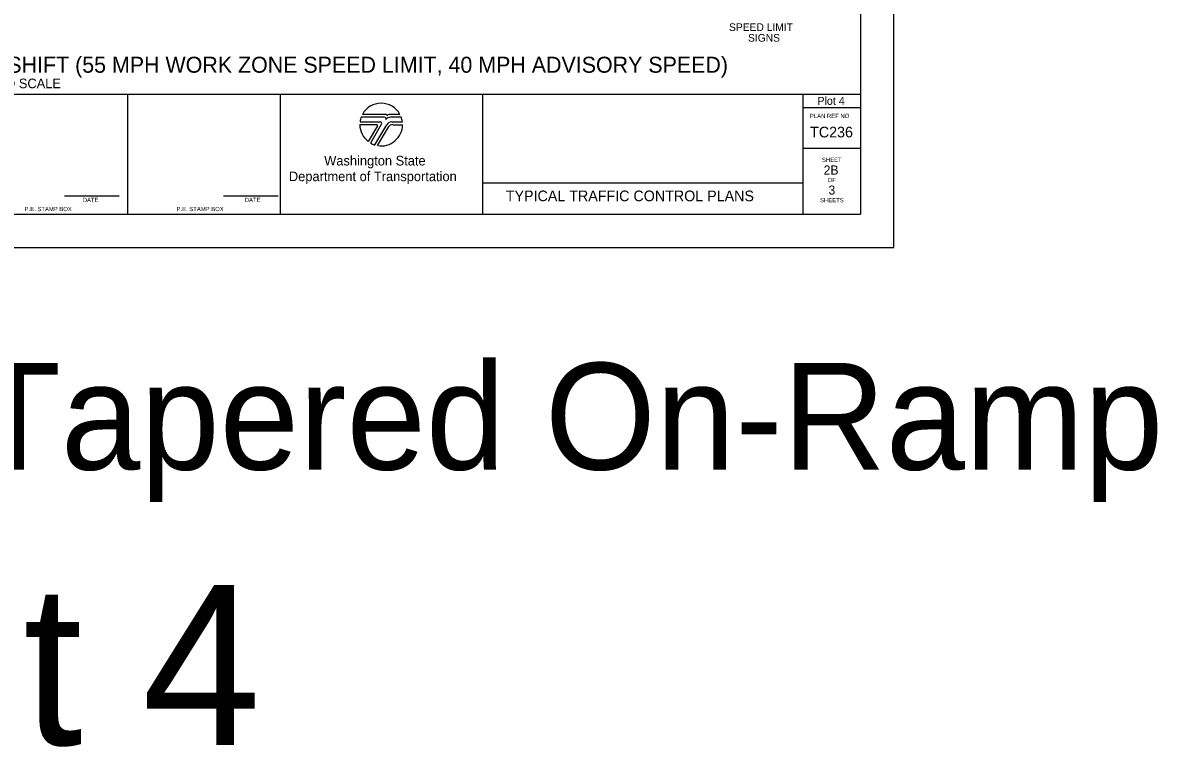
# Model space of a CAD drawing. Extents: x 99999 to 100116, y 99995 to 100013.
# Drawn here: x 100067.9 to 100078.53, y 99995.01 to 100001.79 of the extents above; entities that cross this region are included whole.
import ezdxf

# ---------------------------------------------------------------- set-up
doc = ezdxf.new("R2010")
doc.units = 0
for name, color, linetype in [('SH_DE_DetailHeading1Text', 7, 'Continuous'), ('SH_GI_PlotLimits', 7, 'Continuous'), ('SH_GI_SheetBorder', 7, 'Continuous'), ('SH_GI_SheetLocationText', 7, 'Continuous'), ('SH_GI_SheetTextInCells', 7, 'Continuous'), ('SH_GI_TitleBlockText', 7, 'Continuous'), ('SH_GI_WSDOTLogo', 7, 'Continuous'), ('TR_SN_ConstructionSigns', 7, 'Continuous')]:
    doc.layers.add(name, color=color, linetype=linetype)

msp = doc.modelspace()

# ---------------------------------------------------------------- linework, layer by layer
at = {"layer": 'SH_GI_PlotLimits'}
msp.add_lwpolyline([(100059.062, 99999.687), (100076.062, 99999.687), (100076.062, 100010.687), (100059.062, 100010.687)], close=True, dxfattribs=at)
at = {"layer": 'SH_GI_SheetBorder'}
for p, q in [((100075.75, 100010.375), (100075.75, 100000)), ((100060, 100001.126), (100075.75, 100001.126)), ((100068.883, 100000), (100068.883, 100001.126)), ((100070.309, 100001.126), (100070.309, 100000)), ((100072.205, 100001.126), (100072.205, 100000)), ((100075.208, 100001.126), (100075.208, 100000)), ((100075.208, 100001.001), (100075.75, 100001.001)), ((100075.208, 100000.618), (100075.75, 100000.618)), ((100072.205, 100000.295), (100075.208, 100000.295)), ((100068.29, 100000.173), (100068.802, 100000.173)), ((100069.78, 100000.173), (100070.291, 100000.173)), ((100060, 100000), (100075.75, 100000))]:
    msp.add_line(p, q, dxfattribs=at)
at = {"layer": 'SH_GI_WSDOTLogo'}
for p, q in [((100071.303, 100000.935), (100071.081, 100000.935)), ((100071.433, 100000.935), (100071.335, 100000.935)), ((100071.057, 100000.84), (100071.215, 100000.84)), ((100071.059, 100000.866), (100071.25, 100000.866)), ((100071.289, 100000.909), (100071.07, 100000.909)), ((100071.222, 100000.828), (100071.136, 100000.681)), ((100071.261, 100000.846), (100071.157, 100000.667)), ((100071.199, 100000.649), (100071.309, 100000.839)), ((100071.445, 100000.909), (100071.343, 100000.909)), ((100071.343, 100000.909), (100071.343, 100000.909)), ((100071.356, 100000.866), (100071.456, 100000.866)), ((100071.365, 100000.839), (100071.457, 100000.839)), ((100071.224, 100000.643), (100071.324, 100000.816))]:
    msp.add_line(p, q, dxfattribs=at)
for centre, radius, start, end in [((100071.257, 100000.84), 0.2, 28.4787, 151.532), ((100071.303, 100000.926), 0.00903, 329.8742, 90.0033), ((100071.335, 100000.907), 0.0287, 90.0072, 148.1676), ((100071.257, 100000.84), 0.2, 179.9986, 232.8433), ((100071.257, 100000.84), 0.2, 159.696, 172.5057), ((100071.215, 100000.832), 0.0082, 329.7436, 90), ((100071.257, 100000.84), 0.2, 260.5455, 359.8086), ((100071.25, 100000.853), 0.0131, 329.7683, 90), ((100071.289, 100000.895), 0.0148, 327.8418, 89.9985), ((100071.343, 100000.861), 0.0484, 89.9953, 147.8238), ((100071.356, 100000.812), 0.0542, 90, 149.9974), ((100071.365, 100000.792), 0.0476, 90, 150.0543), ((100071.257, 100000.84), 0.2, 7.4943, 20.2941), ((100071.257, 100000.84), 0.2, 239.7929, 253.0448)]:
    msp.add_arc(centre, radius, start, end, dxfattribs=at)

# ---------------------------------------------------------------- texts
at = {"layer": 'SH_DE_DetailHeading1Text'}
for s, height, p in [("FREEWAY (2 LANES): SINGLE RIGHT LANE CLOSURE, 4' MAX LEFT SHOULDER SHIFT (55 MPH WORK ZONE SPEED LIMIT, 40 MPH ADVISORY SPEED)", 0.15, (100060.091, 100001.326)), ('NOT TO SCALE', 0.09, (100067.373, 100001.181))]:
    msp.add_text(s, height=height, rotation=360, dxfattribs=at).set_placement(p)
at = {"layer": 'SH_GI_SheetBorder'}
msp.add_text('PLAN REF NO', height=0.04003, dxfattribs=at).set_placement((100075.275, 100000.901))
at = {"layer": 'SH_GI_SheetLocationText'}
for s, height, p in [('Plot 4', 0.075, (100075.345, 100001.025)), ('Right Ramps: Tapered On-Ramp', 1, (100058.967, 99997.607)), ('Plot 4', 1.5, (100065.001, 99995.027))]:
    msp.add_text(s, height=height, dxfattribs=at).set_placement(p)
at = {"layer": 'SH_GI_SheetTextInCells'}
for s, height, p in [('Washington State', 0.09007, (100070.723, 100000.457)), ('SHEET', 0.04, (100075.388, 100000.49)), ('Department of Transportation', 0.09007, (100070.392, 100000.31)), ('OF', 0.04, (100075.441, 100000.301)), ('DATE', 0.04, (100068.46, 100000.114)), ('DATE', 0.04, (100069.979, 100000.114)), ('SHEETS', 0.04, (100075.37, 100000.112)), ('P.E. STAMP BOX', 0.04003, (100067.915, 100000.029)), ('P.E. STAMP BOX', 0.04003, (100069.339, 100000.029))]:
    msp.add_text(s, height=height, dxfattribs=at).set_placement(p)
at = {"layer": 'SH_GI_TitleBlockText'}
for s, height, p in [('TC236', 0.1, (100075.277, 100000.72)), ('2B', 0.085, (100075.404, 100000.372)), ('TYPICAL TRAFFIC CONTROL PLANS', 0.1, (100072.425, 100000.122)), ('3', 0.085, (100075.449, 100000.184))]:
    msp.add_text(s, height=height, dxfattribs=at).set_placement(p)
at = {"layer": 'TR_SN_ConstructionSigns'}
for s, p in [('SPEED LIMIT', (100074.517, 100001.717)), ('SIGNS', (100074.695, 100001.617))]:
    msp.add_text(s, height=0.072, dxfattribs=at).set_placement(p)

doc.saveas('drawing.dxf')
